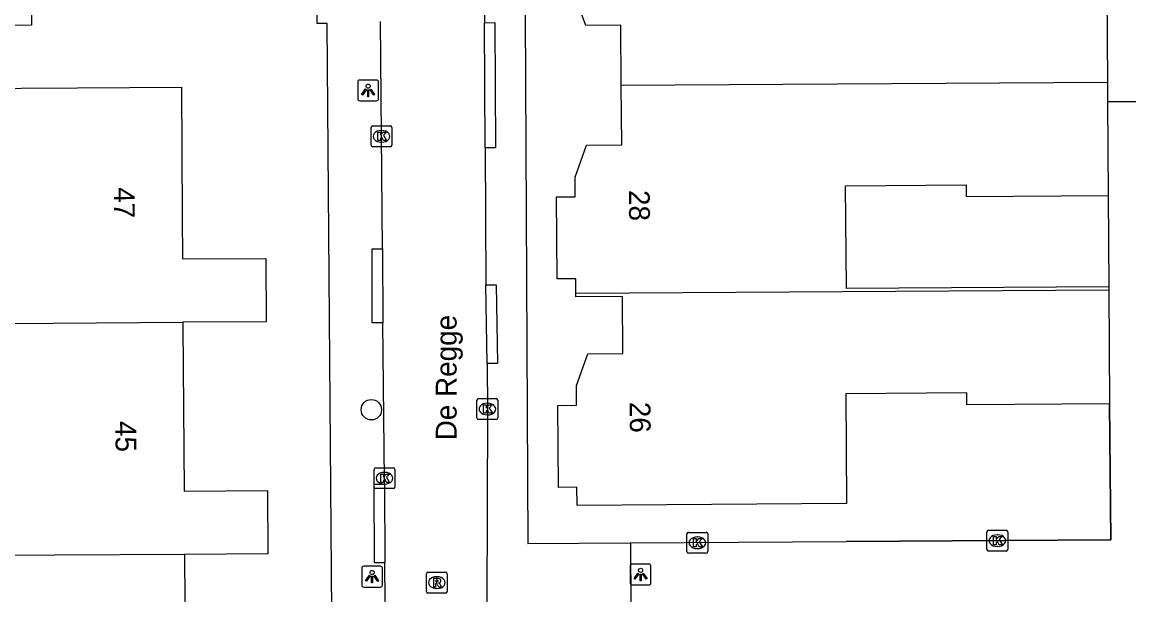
# Model space of a CAD drawing. Extents: x 157321 to 158827, y 386650 to 388532.
# Drawn here: x 157916.1 to 157969.2, y 387536.5 to 387564 of the extents above; entities that cross this region are included whole.
import ezdxf

# ---------------------------------------------------------------- set-up
doc = ezdxf.new("R2010")
doc.units = 0
for name, color, linetype in [('IMGEO_Boom', 7, 'Continuous'), ('IMGEO_Kolk', 7, 'Continuous'), ('IMGEO_Lichtpunt', 7, 'Continuous'), ('IMGEO_Muur', 7, 'Continuous'), ('IMGEO_Openbare_ruimte_label', 7, 'Continuous'), ('IMGEO_Pand', 7, 'Continuous'), ('IMGEO_Pand_nummerreeks', 7, 'Continuous'), ('IMGEO_Rijbaan_lokaal_open', 7, 'Continuous'), ('IMGEO_Rioolput', 7, 'Continuous'), ('IMGEO_Voetpad_open', 7, 'Continuous')]:
    doc.layers.add(name, color=color, linetype=linetype)

msp = doc.modelspace()

# ---------------------------------------------------------------- linework, layer by layer
at = {"layer": 'IMGEO_Boom'}
msp.add_circle((157932.829, 387545.388), 0.489, dxfattribs=at)
at = {"layer": 'IMGEO_Kolk'}
for p, q in [((157932.818, 387558.086), (157932.818, 387558.938)), ((157932.893, 387559.012), (157933.745, 387559.012)), ((157933.819, 387558.938), (157933.819, 387558.086)), ((157933.306, 387558.792), (157933.331, 387558.792)), ((157933.745, 387558.012), (157932.893, 387558.012)), ((157933.329, 387558.232), (157933.304, 387558.232)), ((157937.9, 387544.994), (157937.9, 387545.846)), ((157937.975, 387545.92), (157938.827, 387545.92)), ((157938.388, 387545.7), (157938.413, 387545.7)), ((157938.901, 387545.846), (157938.901, 387544.994)), ((157938.411, 387545.14), (157938.386, 387545.14)), ((157938.827, 387544.92), (157937.975, 387544.92)), ((157932.962, 387541.674), (157932.962, 387542.526)), ((157933.037, 387542.6), (157933.889, 387542.6)), ((157933.963, 387542.526), (157933.963, 387541.674)), ((157933.45, 387542.38), (157933.475, 387542.38)), ((157933.889, 387541.6), (157933.037, 387541.6)), ((157933.473, 387541.82), (157933.448, 387541.82)), ((157947.988, 387538.576), (157947.988, 387539.428)), ((157948.063, 387539.502), (157948.915, 387539.502)), ((157948.476, 387539.282), (157948.501, 387539.282)), ((157948.989, 387539.428), (157948.989, 387538.576)), ((157962.396, 387538.677), (157962.396, 387539.529)), ((157962.471, 387539.603), (157963.323, 387539.603)), ((157962.884, 387539.383), (157962.909, 387539.383)), ((157963.397, 387539.529), (157963.397, 387538.677)), ((157948.499, 387538.722), (157948.474, 387538.722)), ((157962.907, 387538.823), (157962.882, 387538.823)), ((157948.915, 387538.502), (157948.063, 387538.502)), ((157963.323, 387538.603), (157962.471, 387538.603))]:
    msp.add_line(p, q, dxfattribs=at)
for points in [[(157932.818, 387558.086), (157932.818, 387558.938)], [(157932.893, 387559.012), (157933.745, 387559.012)], [(157933.819, 387558.938), (157933.819, 387558.086)], [(157933.139, 387558.712), (157933.262, 387558.712), (157933.262, 387558.561), (157933.392, 387558.712), (157933.556, 387558.712), (157933.41, 387558.561), (157933.563, 387558.312), (157933.411, 387558.312), (157933.326, 387558.476), (157933.262, 387558.409), (157933.262, 387558.312), (157933.139, 387558.312), (157933.139, 387558.712)], [(157933.745, 387558.012), (157932.893, 387558.012)], [(157937.9, 387544.994), (157937.9, 387545.846)], [(157937.975, 387545.92), (157938.827, 387545.92)], [(157938.221, 387545.62), (157938.344, 387545.62), (157938.344, 387545.469), (157938.474, 387545.62), (157938.638, 387545.62), (157938.492, 387545.469), (157938.645, 387545.22), (157938.493, 387545.22), (157938.408, 387545.384), (157938.344, 387545.317), (157938.344, 387545.22), (157938.221, 387545.22), (157938.221, 387545.62)], [(157938.901, 387545.846), (157938.901, 387544.994)], [(157938.827, 387544.92), (157937.975, 387544.92)], [(157932.962, 387541.674), (157932.962, 387542.526)], [(157933.037, 387542.6), (157933.889, 387542.6)], [(157933.963, 387542.526), (157933.963, 387541.674)], [(157933.283, 387542.3), (157933.406, 387542.3), (157933.406, 387542.149), (157933.536, 387542.3), (157933.7, 387542.3), (157933.554, 387542.149), (157933.707, 387541.9), (157933.555, 387541.9), (157933.47, 387542.064), (157933.406, 387541.997), (157933.406, 387541.9), (157933.283, 387541.9), (157933.283, 387542.3)], [(157933.889, 387541.6), (157933.037, 387541.6)], [(157947.988, 387538.576), (157947.988, 387539.428)], [(157948.063, 387539.502), (157948.915, 387539.502)], [(157948.989, 387539.428), (157948.989, 387538.576)], [(157962.396, 387538.677), (157962.396, 387539.529)], [(157962.471, 387539.603), (157963.323, 387539.603)], [(157962.717, 387539.303), (157962.84, 387539.303), (157962.84, 387539.152), (157962.97, 387539.303), (157963.134, 387539.303), (157962.988, 387539.152), (157963.141, 387538.903), (157962.989, 387538.903), (157962.904, 387539.067), (157962.84, 387539), (157962.84, 387538.903), (157962.717, 387538.903), (157962.717, 387539.303)], [(157963.397, 387539.529), (157963.397, 387538.677)], [(157948.309, 387539.202), (157948.432, 387539.202), (157948.432, 387539.051), (157948.562, 387539.202), (157948.726, 387539.202), (157948.58, 387539.051), (157948.733, 387538.802), (157948.581, 387538.802), (157948.496, 387538.966), (157948.432, 387538.899), (157948.432, 387538.802), (157948.309, 387538.802), (157948.309, 387539.202)], [(157948.915, 387538.502), (157948.063, 387538.502)], [(157963.323, 387538.603), (157962.471, 387538.603)]]:
    msp.add_lwpolyline(points, dxfattribs=at)
for centre, start, end in [((157932.895, 387558.936), 91.552, 178.448), ((157932.895, 387558.936), 91.552, 178.448), ((157933.743, 387558.936), 1.552, 88.448), ((157933.743, 387558.936), 1.552, 88.448), ((157932.895, 387558.088), 181.552, 268.448), ((157932.895, 387558.088), 181.552, 268.448), ((157933.743, 387558.088), 271.552, 358.448), ((157933.743, 387558.088), 271.552, 358.448), ((157937.977, 387545.844), 91.552, 178.448), ((157937.977, 387545.844), 91.552, 178.448), ((157938.825, 387545.844), 1.552, 88.448), ((157938.825, 387545.844), 1.552, 88.448), ((157937.977, 387544.996), 181.552, 268.448), ((157937.977, 387544.996), 181.552, 268.448), ((157938.825, 387544.996), 271.552, 358.448), ((157938.825, 387544.996), 271.552, 358.448), ((157933.039, 387542.524), 91.552, 178.448), ((157933.039, 387542.524), 91.552, 178.448), ((157933.887, 387542.524), 1.552, 88.448), ((157933.887, 387542.524), 1.552, 88.448), ((157933.039, 387541.676), 181.552, 268.448), ((157933.039, 387541.676), 181.552, 268.448), ((157933.887, 387541.676), 271.552, 358.448), ((157933.887, 387541.676), 271.552, 358.448), ((157948.065, 387539.426), 91.552, 178.448), ((157948.065, 387539.426), 91.552, 178.448), ((157948.913, 387539.426), 1.552, 88.448), ((157948.913, 387539.426), 1.552, 88.448), ((157962.473, 387539.527), 91.552, 178.448), ((157962.473, 387539.527), 91.552, 178.448), ((157963.321, 387539.527), 1.552, 88.448), ((157963.321, 387539.527), 1.552, 88.448), ((157948.065, 387538.578), 181.552, 268.448), ((157948.065, 387538.578), 181.552, 268.448), ((157948.913, 387538.578), 271.552, 358.448), ((157948.913, 387538.578), 271.552, 358.448), ((157962.473, 387538.679), 181.552, 268.448), ((157962.473, 387538.679), 181.552, 268.448), ((157963.321, 387538.679), 271.552, 358.448), ((157963.321, 387538.679), 271.552, 358.448)]:
    msp.add_arc(centre, 0.0765, start, end, dxfattribs=at)
for centre, major_axis, ratio, start_param, end_param in [((157933.305, 387558.512), (-0.387, 0.002), 0.722429, 4.712389, 7.853982), ((157933.33, 387558.512), (-0.39, 0.002), 0.717154, 1.570796, 4.712389), ((157938.387, 387545.42), (-0.387, 0.002), 0.722429, 4.712389, 7.853982), ((157938.412, 387545.42), (-0.39, 0.002), 0.717154, 1.570796, 4.712389), ((157933.449, 387542.1), (-0.387, 0.002), 0.722429, 4.712389, 7.853982), ((157933.474, 387542.1), (-0.39, 0.002), 0.717154, 1.570796, 4.712389), ((157948.475, 387539.002), (-0.387, 0.002), 0.722429, 4.712389, 7.853982), ((157948.5, 387539.002), (-0.39, 0.002), 0.717154, 1.570796, 4.712389), ((157962.883, 387539.103), (-0.387, 0.002), 0.722429, 4.712389, 7.853982), ((157962.908, 387539.103), (-0.39, 0.002), 0.717154, 1.570796, 4.712389)]:
    msp.add_ellipse(centre, major_axis=major_axis, ratio=ratio, start_param=start_param, end_param=end_param, dxfattribs=at)
at = {"layer": 'IMGEO_Lichtpunt'}
for p, q in [((157932.176, 387561.12), (157932.176, 387560.313)), ((157932.176, 387561.12), (157932.176, 387560.313)), ((157933.078, 387561.215), (157932.27, 387561.215)), ((157933.078, 387561.215), (157932.27, 387561.215)), ((157933.172, 387560.313), (157933.172, 387561.12)), ((157933.172, 387560.313), (157933.172, 387561.12)), ((157932.27, 387560.219), (157933.078, 387560.219)), ((157932.27, 387560.219), (157933.078, 387560.219)), ((157932.367, 387537.777), (157932.367, 387536.97)), ((157932.367, 387537.777), (157932.367, 387536.97)), ((157933.269, 387537.872), (157932.461, 387537.872)), ((157933.269, 387537.872), (157932.461, 387537.872)), ((157933.363, 387536.97), (157933.363, 387537.777)), ((157933.363, 387536.97), (157933.363, 387537.777)), ((157945.261, 387537.881), (157945.261, 387537.074)), ((157945.261, 387537.881), (157945.261, 387537.074)), ((157946.163, 387537.976), (157945.355, 387537.976)), ((157946.163, 387537.976), (157945.355, 387537.976)), ((157946.257, 387537.074), (157946.257, 387537.881)), ((157946.257, 387537.074), (157946.257, 387537.881)), ((157932.461, 387536.876), (157933.269, 387536.876)), ((157932.461, 387536.876), (157933.269, 387536.876)), ((157945.355, 387536.98), (157946.163, 387536.98)), ((157945.355, 387536.98), (157946.163, 387536.98))]:
    msp.add_line(p, q, dxfattribs=at)
for points in [[(157932.55, 387560.784), (157932.589, 387560.756), (157932.401, 387560.494), (157932.363, 387560.521), (157932.55, 387560.784)], [(157932.652, 387560.736), (157932.699, 387560.736), (157932.699, 387560.414), (157932.652, 387560.414), (157932.652, 387560.736)], [(157932.762, 387560.756), (157932.8, 387560.783), (157932.987, 387560.521), (157932.948, 387560.493), (157932.762, 387560.756)], [(157932.741, 387537.441), (157932.78, 387537.413), (157932.592, 387537.151), (157932.554, 387537.178), (157932.741, 387537.441)], [(157932.843, 387537.393), (157932.89, 387537.393), (157932.89, 387537.071), (157932.843, 387537.071), (157932.843, 387537.393)], [(157932.953, 387537.413), (157932.991, 387537.44), (157933.178, 387537.178), (157933.139, 387537.15), (157932.953, 387537.413)], [(157945.635, 387537.545), (157945.674, 387537.517), (157945.486, 387537.255), (157945.448, 387537.282), (157945.635, 387537.545)], [(157945.737, 387537.497), (157945.784, 387537.497), (157945.784, 387537.175), (157945.737, 387537.175), (157945.737, 387537.497)], [(157945.847, 387537.517), (157945.885, 387537.544), (157946.072, 387537.282), (157946.033, 387537.254), (157945.847, 387537.517)]]:
    msp.add_lwpolyline(points, dxfattribs=at)
for centre in [(157932.675, 387560.918), (157932.866, 387537.575), (157945.76, 387537.679)]:
    msp.add_circle(centre, 0.0994, dxfattribs=at)
for centre, start, end in [((157932.27, 387561.12), 90, 180), ((157932.27, 387561.12), 90, 180), ((157933.078, 387561.12), 0, 90), ((157933.078, 387561.12), 0, 90), ((157932.27, 387560.313), 180, 270), ((157932.27, 387560.313), 180, 270), ((157933.078, 387560.313), 270, 0), ((157933.078, 387560.313), 270, 360), ((157932.461, 387537.777), 90, 180), ((157932.461, 387537.777), 90, 180), ((157933.269, 387537.777), 0, 90), ((157933.269, 387537.777), 0, 90), ((157945.355, 387537.881), 90, 180), ((157945.355, 387537.881), 90, 180), ((157946.163, 387537.881), 0, 90), ((157946.163, 387537.881), 0, 90), ((157932.461, 387536.97), 180, 270), ((157932.461, 387536.97), 180, 270), ((157933.269, 387536.97), 270, 0), ((157933.269, 387536.97), 270, 360), ((157945.355, 387537.074), 180, 270), ((157945.355, 387537.074), 180, 270), ((157946.163, 387537.074), 270, 0), ((157946.163, 387537.074), 270, 360)]:
    msp.add_arc(centre, 0.0946, start, end, dxfattribs=at)
at = {"layer": 'IMGEO_Muur'}
for points in [[(158019.271, 387560.48), (157968.192, 387560.166)], [(157968.291, 387545.671), (157968.35, 387539.142), (157955.659, 387539.062)]]:
    msp.add_lwpolyline(points, dxfattribs=at)
at = {"layer": 'IMGEO_Pand'}
for points in [[(157944.835, 387560.964), (157944.817, 387563.844), (157943.128, 387563.834), (157942.564, 387565.354), (157942.558, 387566.303), (157941.661, 387566.298), (157941.634, 387570.231), (157942.533, 387570.237), (157942.528, 387570.956)], [(157955.475, 387571.046), (157955.51, 387565.94), (157961.306, 387565.98), (157961.303, 387566.549), (157968.148, 387566.596), (157968.156, 387565.382), (157968.185, 387561.119)], [(157910.856, 387569.764), (157916.451, 387569.818), (157916.508, 387563.848), (157910.899, 387563.794)], [(157944.835, 387560.964), (157968.185, 387561.119)], [(157968.185, 387561.119), (157968.191, 387560.32), (157968.192, 387560.166)], [(157913.387, 387549.517), (157911.292, 387549.504), (157911.259, 387553.885), (157913.355, 387553.9), (157913.304, 387560.806), (157918.707, 387560.841), (157923.706, 387560.874), (157923.748, 387554.675), (157923.762, 387552.626), (157927.761, 387552.653), (157927.774, 387549.61), (157923.776, 387549.584)], [(157942.652, 387550.965), (157942.647, 387551.675), (157941.75, 387551.67), (157941.726, 387555.599), (157942.624, 387555.604), (157942.618, 387556.554), (157943.163, 387558.09), (157944.852, 387558.101), (157944.835, 387560.964)], [(157968.192, 387560.166), (157968.223, 387555.677)], [(157968.253, 387551.287), (157955.653, 387551.207), (157955.611, 387556.14), (157961.392, 387556.188), (157961.396, 387555.62), (157968.223, 387555.677)], [(157968.291, 387545.671), (157961.427, 387545.626), (157961.424, 387546.197), (157955.612, 387546.158), (157955.647, 387540.888), (157942.721, 387540.786), (157942.704, 387541.665), (157941.819, 387541.661), (157941.787, 387545.597), (157942.684, 387545.602), (157942.678, 387546.552), (157943.224, 387548.078), (157944.913, 387548.089), (157944.896, 387550.821), (157942.653, 387550.808), (157942.652, 387550.965)], [(157968.254, 387551.127), (157942.652, 387550.965)], [(157968.253, 387551.287), (157968.254, 387551.127)], [(157968.254, 387551.127), (157968.291, 387545.671)], [(157913.387, 387549.517), (157923.776, 387549.584)], [(157923.776, 387549.584), (157923.777, 387549.418), (157923.825, 387543.516), (157923.841, 387541.471), (157927.839, 387541.503), (157927.855, 387538.468), (157923.853, 387538.443)], [(157923.853, 387538.443), (157911.374, 387538.367)], [(157923.853, 387538.443), (157923.854, 387538.281), (157923.895, 387532.364), (157923.909, 387530.327), (157927.911, 387530.355), (157927.922, 387527.318), (157923.923, 387527.292)]]:
    msp.add_lwpolyline(points, dxfattribs=at)
at = {"layer": 'IMGEO_Rijbaan_lokaal_open'}
for points in [[(157938.194, 387576.452), (157938.246, 387568.213), (157938.26, 387563.966)], [(157933.372, 387553.11), (157933.268, 387564.016)], [(157938.296, 387557.958), (157938.26, 387563.966)], [(157938.296, 387557.958), (157938.327, 387551.379)], [(157933.372, 387553.11), (157933.374, 387549.564)], [(157938.384, 387547.602), (157938.327, 387551.379)], [(157933.466, 387541.813), (157933.465, 387542.004), (157933.374, 387549.564)], [(157938.384, 387547.602), (157938.4, 387545.383), (157938.378, 387536.008)], [(157933.466, 387541.813), (157933.482, 387538.043)], [(157933.54, 387530.546), (157933.482, 387538.043)]]:
    msp.add_lwpolyline(points, dxfattribs=at)
at = {"layer": 'IMGEO_Rioolput'}
for p, q in [((157935.471, 387536.663), (157935.471, 387537.515)), ((157935.546, 387537.589), (157936.398, 387537.589)), ((157935.959, 387537.369), (157935.984, 387537.369)), ((157936.472, 387537.515), (157936.472, 387536.663)), ((157936.398, 387536.589), (157935.546, 387536.589)), ((157935.982, 387536.809), (157935.957, 387536.809))]:
    msp.add_line(p, q, dxfattribs=at)
for points in [[(157935.471, 387536.663), (157935.471, 387537.515)], [(157935.546, 387537.589), (157936.398, 387537.589)], [(157936.06, 387537.287), (157935.808, 387537.289), (157935.808, 387536.889)], [(157935.986, 387537.208), (157935.932, 387537.208), (157935.932, 387537.127)], [(157935.932, 387537.127), (157935.984, 387537.127)], [(157936.472, 387537.515), (157936.472, 387536.663)], [(157936.398, 387536.589), (157935.546, 387536.589)], [(157935.808, 387536.889), (157935.932, 387536.889), (157935.932, 387537.051), (157935.943, 387537.051)], [(157935.99, 387537.022), (157936.061, 387536.889), (157936.201, 387536.889), (157936.136, 387537.015)]]:
    msp.add_lwpolyline(points, dxfattribs=at)
for centre, radius, start, end in [((157935.548, 387537.513), 0.0765, 91.552, 178.448), ((157935.548, 387537.513), 0.0765, 91.552, 178.448), ((157935.968, 387537.316), 0.19, 274.7715, 282.9687), ((157935.992, 387537.112), 0.0964, 77.0061, 93.1865), ((157936.006, 387537.169), 0.0378, 276.6634, 79.6772), ((157936.059, 387537.177), 0.109, 350.3612, 89.416), ((157936.057, 387537.177), 0.112, 277.5842, 350.9817), ((157936.396, 387537.513), 0.0765, 1.552, 88.448), ((157936.396, 387537.513), 0.0765, 1.552, 88.448), ((157935.548, 387536.665), 0.0765, 181.552, 268.448), ((157935.548, 387536.665), 0.0765, 181.552, 268.448), ((157935.942, 387536.998), 0.0533, 26.0293, 88.6989), ((157936.041, 387536.962), 0.108, 29.5134, 73.7905), ((157936.396, 387536.665), 0.0765, 271.552, 358.448), ((157936.396, 387536.665), 0.0765, 271.552, 358.448)]:
    msp.add_arc(centre, radius, start, end, dxfattribs=at)
for centre, major_axis, ratio, start_param, end_param in [((157935.958, 387537.089), (-0.387, 0.002), 0.722429, 4.712389, 7.853982), ((157935.983, 387537.089), (-0.39, 0.002), 0.717154, 1.570796, 4.712389)]:
    msp.add_ellipse(centre, major_axis=major_axis, ratio=ratio, start_param=start_param, end_param=end_param, dxfattribs=at)
at = {"layer": 'IMGEO_Voetpad_open'}
for points in [[(158026.142, 387481.499), (158021.016, 387481.457), (158000, 387481.305), (157990.079, 387481.233), (157962.562, 387496.218), (157955.633, 387500), (157931.114, 387513.382), (157930.704, 387563.922), (157930.223, 387563.93), (157929.973, 387592.849)], [(157940.07, 387592.871), (157940.347, 387538.966), (157945.278, 387538.997)], [(157938.26, 387563.966), (157938.759, 387563.968), (157938.795, 387557.96), (157938.296, 387557.958)], [(157968.192, 387560.166), (158019.271, 387560.48)], [(157968.223, 387555.677), (157968.253, 387551.287)], [(157933.374, 387549.564), (157932.875, 387549.564), (157932.873, 387553.11), (157933.372, 387553.11)], [(157938.327, 387551.379), (157938.826, 387551.386), (157938.883, 387547.609), (157938.384, 387547.602)], [(157945.278, 387538.997), (157955.659, 387539.062), (157968.35, 387539.142), (157968.291, 387545.671)], [(157933.482, 387538.043), (157932.983, 387538.041), (157932.967, 387541.811), (157933.466, 387541.813)], [(157945.278, 387538.997), (157945.294, 387535.957)]]:
    msp.add_lwpolyline(points, dxfattribs=at)

# ---------------------------------------------------------------- texts
at = {"layer": 'IMGEO_Openbare_ruimte_label'}
msp.add_text('De Regge', height=1, rotation=90, dxfattribs=at).set_placement((157936.924, 387543.919))
at = {"layer": 'IMGEO_Pand_nummerreeks'}
for s, rotation, p in [('47', 270.3894, (157920.459, 387556.066)), ('28', 270.3903, (157945.2, 387555.931)), ('26', 270.3903, (157945.235, 387545.764)), ('45', 270.3894, (157920.536, 387544.842))]:
    msp.add_text(s, height=1, rotation=rotation, dxfattribs=at).set_placement(p)

doc.saveas('drawing.dxf')
